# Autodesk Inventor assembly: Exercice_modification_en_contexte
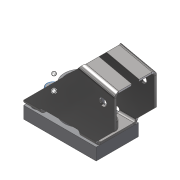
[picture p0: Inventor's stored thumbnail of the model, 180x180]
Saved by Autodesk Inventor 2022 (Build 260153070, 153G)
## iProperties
Created: 2018-06
Part Number: Exercice_modification_en_contexte
Material: Générique
Document SubType Name: Assembly
Designer: Fabian Perrée
Mass: 105.136 g
Surface Area: 173.547 cm^2
Volume: 19.7524 cm^3
Density: 5.32267 g/cm^3
Author: Fabian Perrée
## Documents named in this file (5)
- C:\Users\Fabian\Google Drive\01_Giup\01_Clients\07_ENI\Manuscrit\Fichiers_exercice\Chapitre_06\Exercice_modification_en_contexte\Exercice_modification_en_contexte.iam
- C:\Users\Fabian\Google Drive\01_Giup\01_Clients\07_ENI\Manuscrit\Fichiers_exercice\Chapitre_06\Exercice_modification_en_contexte\Composants\Etrier_tole.ipt
- C:\Users\Fabian\Google Drive\01_Giup\01_Clients\07_ENI\Manuscrit\Fichiers_exercice\CC\ISO 4762 - M5 x 8ISO.ipt
- C:\Users\Fabian\Google Drive\01_Giup\01_Clients\07_ENI\Manuscrit\Fichiers_exercice\Chapitre_06\Exercice_modification_en_contexte\Composants\Chapeau_capteur.ipt
- C:\Users\Fabian\Google Drive\01_Giup\01_Clients\07_ENI\Manuscrit\Fichiers_exercice\Chapitre_06\Exercice_modification_en_contexte\Composants\Bille_18.ipt
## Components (5 placed, 4 different names)
1. Etrier_tole:1 — Logement:3, Logement:4
2. Chapeau_capteur:1 — Logement:3, Logement:4
3. Bille_18:1
4. ISO 4762 M5 x 8:1
5. ISO 4762 M5 x 8:2
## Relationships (2: Insert 2)
- Logement:3 [Insert]: Etrier_tole:1 ↔ Chapeau_capteur:1
- Logement:4 [Insert]: Etrier_tole:1 ↔ Chapeau_capteur:1
